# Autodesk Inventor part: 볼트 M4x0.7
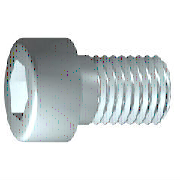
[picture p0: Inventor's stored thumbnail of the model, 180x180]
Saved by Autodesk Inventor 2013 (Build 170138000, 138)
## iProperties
IsCustomPart: 1
Created: 2015-10
Part Number: 볼트 M4x0.7
Material: 스테인리스강
Description: 6각머리 태핑 나사
Document SubType Name: Modeling
Standard: KS B 1003
Designer: mdu
Standards Organization: KS
Language: ko-KR
Size Designation: M 4 x 16
Categories: <MemberInstance><Categories><Category DisplayName="조임쇠" InternalName="e4da775c-781d-43d5-af7c-5136215cf5a6" Mnemonic="FSTN"><Category DisplayName="볼트" InternalN
Density: 8.08 g/cm^3
Mass: 2.70334 g
Surface Area: 3.81118 cm^2
Volume: 0.334572 cm^3
Author: mdu
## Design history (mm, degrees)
sketch "스케치1"
  geometry: L1 (-1, 0)-(14, 0); L2 (14, 0)-(14, 2); L3 (14, 2)-(1.75, 2); L4 (1.75, 2)-(1.32, 2); L5 (1.32, 2)-(0, 2); L6 (0, 2)-(0, 3.5); L7 (0, 3.5)-(-4, 3.5); L8 (-4, 3.5)-(-4, 1.732); L9 (-4, 1.732)-(-2, 1.732); L10 (-2, 1.732)-(-1, 0); L11 (-7.6, 0)-(17.6, 0) reference; L12 (0, -0.7)-(0, 4.2) reference; L13 (1.75, 2)-(0, 2)
  constraints: 22 end point, 6 parallel, 2 collinear, 2 perpendicular, 1 horizontal, 1 point on line
  dimensions: "d1" = 12.25 distance from line of L3.end L2 (= GEL); "d2" = 0.42952 distance of L4.end L3.end (computed from GAL); "d3" = 4 distance between parallel lines of L8 L6 (= KOH); "d4" = 2 distance of L8.end L9.end (= INTI); "d5" = 60 deg angle of L10 L1; "d6" = 4 diameter of L3 L1 (= GD); "d7" = 4 diameter of L5 L1 (= BDM); "d8" = 3.4641 diameter of L9 L1 (= 1.1547 x SW); "d9" = 7 diameter of L7 L1 (= KOD); "d26" = 14 distance between parallel lines of L12 L2 (= NLG)
revolve "본체" sketch "스케치1" stored, may be unused: angle "d10" = 90 deg
sketch "스케치2"
  geometry: L1 (0, -4.9)-(0, 4.9) reference; L2 (-4.9, 0)-(4.9, 0) reference; L3 (1.732, 0)-(0.866, -1.5); L4 (0.866, -1.5)-(-0.866, -1.5); L5 (-0.866, -1.5)-(-1.732, 0); L6 (-1.732, 0)-(-0.866, 1.5); L7 (-0.866, 1.5)-(0.866, 1.5); L8 (0.866, 1.5)-(1.732, 0); 2 further points
  constraints: 12 end point, 1 coincident, 1 horizontal alignment, 1 point on line, 12 other
extrude "슬롯" join sketch "스케치2" stored distance "d11" = 10; taper "d12" = 0 deg
workplane "Work Plane1"
fillet "Fillet2" dims "d30" = 0.1 (= R)
body "Solid1"
fillet "모깎기1" dims "d17" = 0.4 (= RR)
feature "스레드" dims "d13" = 12.25 (= GEL), "d14" = 0
chamfer "모따기1" distance "d15" = 0.42941 (= -0.5 x SPD + 0.5 x GD); stored, may be unused: second distance "d16" = 0.42941 (= GUL), angle "d27" = 45 deg
other parameters: "GD" = 4 (= NND) [user parameter; used in 2 equation terms], "NLG" = 14 [user parameter; used in 1 equation term], "GEL" = 12.25 [user parameter; used in 2 equation terms], "KOD" = 7 [user parameter; used in 1 equation term], "KOH" = 4 [user parameter; used in 1 equation term], "INTI" = 2 [user parameter; used in 1 equation term], "GAL" = 0.42941 (= 0.61345 x PTC) [user parameter; used in 1 equation term], "GUL" = 0.42941 (= 0.61345 x PTC) [user parameter; used in 1 equation term], "BDM" = 4 (= NND) [user parameter; used in 1 equation term], "SW" = 3 [user parameter; used in 2 equation terms], "RR" = 0.4 [user parameter; used in 1 equation term], "SPD" = 3.14117 (= NND - 1.2269 x PTC) [user parameter; used in 1 equation term], "d19" = 0, "d28" = 0, "d29" = 0, "R" = 0.1 [user parameter; used in 1 equation term], "PHH" = 0.2 [user parameter], "GD1" = 3.14117 (= THREADDIA - 1.2269 x PTC) [user parameter], "THREADDIA" = 4 [user parameter; used in 1 equation term], "FAWI" = 45 deg [user parameter], "TPU" = 14.28571 (computed from PTC) [user parameter], "PTC" = 0.7 [user parameter; used in 5 equation terms], "NND" = 4 [user parameter; used in 3 equation terms], "TOA" = 30 deg [user parameter], "E0" = 3.465 (= 1.155 x SW) [user parameter]
